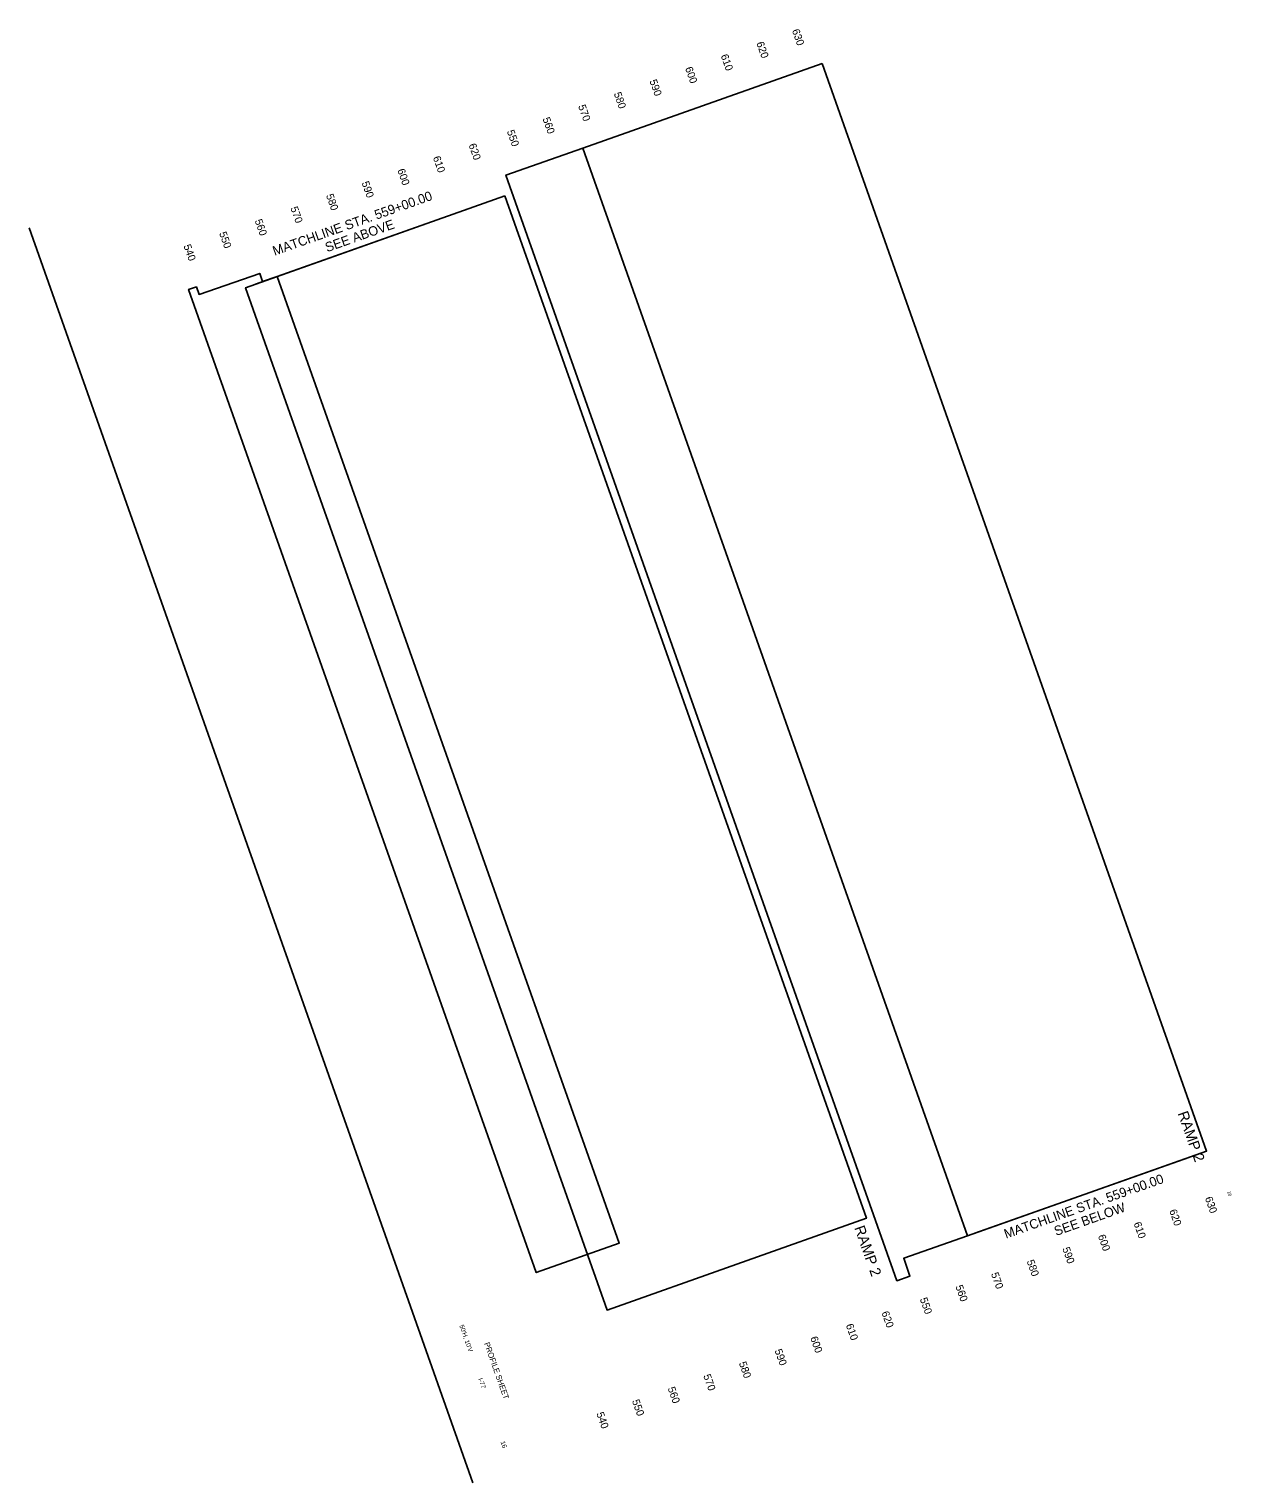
# Model space of a CAD drawing. Extents: x 1990416 to 1992007, y 1125738 to 1127660.
import ezdxf

# ---------------------------------------------------------------- set-up
doc = ezdxf.new("R2010")
doc.units = 0
for name, color, linetype in [('RD_DDB_ElevTX', 7, 'Continuous'), ('RD_DDB_Profile_Lbl', 7, 'Continuous'), ('RD_DDB_Profile_PR', 7, 'Continuous')]:
    doc.layers.add(name, color=color, linetype=linetype)

msp = doc.modelspace()

# ---------------------------------------------------------------- linework, layer by layer
at = {"layer": 'RD_DDB_ElevTX'}
msp.add_line((1990415.9, 1127397.5), (1991002.8, 1125738.3), dxfattribs=at)
at = {"layer": 'RD_DDB_Profile_Lbl'}
for points in [[(1991464.7, 1127614.7), (1991973.4, 1126177), (1991657, 1126065.1), (1991148.4, 1127502.8)], [(1991148.4, 1127502.8), (1991657, 1126065.1), (1991572.7, 1126035.2), (1991581, 1126011.7), (1991563.8, 1126005.6), (1991046.7, 1127467.4)], [(1991045.3, 1127439.8), (1991523.5, 1126088.1), (1991180.4, 1125966.8), (1990702.3, 1127318.4)], [(1990744.2, 1127333.2), (1991196.4, 1126055.1), (1991086.7, 1126016.3), (1990626.8, 1127316.1), (1990637.2, 1127319.5), (1990640.8, 1127309.6), (1990720.9, 1127337.3), (1990724.7, 1127326.5)]]:
    msp.add_lwpolyline(points, close=True, dxfattribs=at)
at = {"layer": 'RD_DDB_Profile_PR'}
for p, q in [((1990998.2, 1127423.1), (1990715.4, 1127323)), ((1991949.8, 1126168.6), (1991667, 1126068.6))]:
    msp.add_line(p, q, dxfattribs=at)

# ---------------------------------------------------------------- texts
at = {"layer": 'RD_DDB_ElevTX'}
for s, height, p in [('630', 10, (1991424.8, 1127658.5)), ('620', 10, (1991377.7, 1127641.8)), ('610', 10, (1991330.6, 1127625.2)), ('600', 10, (1991283.4, 1127608.5)), ('590', 10, (1991236.3, 1127591.8)), ('570', 10, (1991142, 1127558.5)), ('580', 10, (1991189.1, 1127575.1)), ('560', 10, (1991094.9, 1127541.8)), ('550', 10, (1991047.7, 1127525.1)), ('620', 10, (1990997.1, 1127507.2)), ('610', 10, (1990949.9, 1127490.5)), ('600', 10, (1990902.8, 1127473.8)), ('590', 10, (1990855.6, 1127457.2)), ('570', 10, (1990761.4, 1127423.8)), ('580', 10, (1990808.5, 1127440.5)), ('560', 10, (1990714.2, 1127407.1)), ('550', 10, (1990667.1, 1127390.5)), ('540', 10, (1990620, 1127373.8)), ('RAMP 2', 14, (1991935, 1126226.9)), ('16', 4.5, (1992000.6, 1126123.3)), ('620', 10, (1991923.8, 1126098.1)), ('630', 10, (1991971, 1126114.8)), ('610', 10, (1991876.7, 1126081.4)), ('RAMP 2', 14, (1991507.2, 1126075.6)), ('600', 10, (1991829.5, 1126064.8)), ('590', 10, (1991782.4, 1126048.1)), ('580', 10, (1991735.3, 1126031.4)), ('570', 10, (1991688.1, 1126014.7)), ('550', 10, (1991593.9, 1125981.4)), ('560', 10, (1991641, 1125998)), ('620', 10, (1991543.2, 1125963.4)), ("50'H, 10'V", 6, (1990984.9, 1125946.3)), ('610', 10, (1991496, 1125946.8)), ('600', 10, (1991448.9, 1125930.1)), ('PROFILE SHEET', 7.5, (1991017.6, 1125922.7)), ('590', 10, (1991401.8, 1125913.4)), ('580', 10, (1991354.6, 1125896.7)), ('I-77', 6, (1991009.9, 1125875.8)), ('570', 10, (1991307.5, 1125880.1)), ('550', 10, (1991213.2, 1125846.7)), ('560', 10, (1991260.4, 1125863.4)), ('540', 10, (1991166.1, 1125830)), ('16', 6, (1991039.4, 1125792.4))]:
    msp.add_text(s, height=height, rotation=289.482, dxfattribs=at).set_placement(p)
at = {"layer": 'RD_DDB_Profile_PR'}
for s, p in [('MATCHLINE STA. 559+00.00', (1990740.6, 1127360.6)), ('SEE ABOVE', (1990810.1, 1127365.3)), ('MATCHLINE STA. 559+00.00', (1991708.1, 1126061.1)), ('SEE BELOW', (1991774.3, 1126064.7))]:
    msp.add_text(s, height=12.5, rotation=19.482, dxfattribs=at).set_placement(p)

doc.saveas('drawing.dxf')
